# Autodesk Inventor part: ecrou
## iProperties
Created: 2002-03
Part Number: ecrou
Material: Par défaut
Document SubType Name: Modélisation
Designer: User
Control State: 0
Master: False
Checked Out: False
Shininess: 25.0
Length Units: 11269
Angle Units: 11279
Time Units: 11290
Mass Units: 11283
Length Display Precision: 3
Angle Display Precision: 2
Density: 0.0
Volumn: 0.0
Area: 0.0
PropertySet Name: Model Information
Author: User
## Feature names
1. Révolution1 [Revolution]
2. Extrusion1
3. Extrusion2
4. Perçage1 [Hole]
